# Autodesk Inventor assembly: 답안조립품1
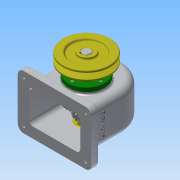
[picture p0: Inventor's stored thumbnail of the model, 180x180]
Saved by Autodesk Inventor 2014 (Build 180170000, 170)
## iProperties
Created: 2016-10
Part Number: 답안조립품1
Document SubType Name: Assembly
Designer: net
Author: net
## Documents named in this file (15)
- C:\Users\net\Desktop\461007V1012\답안조립품1.iam
- C:\Users\net\Desktop\461007V1012\본체.ipt
- C:\Users\net\Desktop\461007V1012\V-벨트풀리.ipt
- C:\Users\net\Desktop\461007V1012\뒤커버.ipt
- C:\Users\net\Desktop\461007V1012\멈춤나사 - M4x10.ipt
- C:\Users\net\Desktop\461007V1012\베어링 6203.ipt
- C:\Users\net\Desktop\461007V1012\볼트 M3 x 8.ipt
- C:\Users\net\Desktop\461007V1012\볼트 M3 x 10.ipt
- C:\Users\net\Desktop\461007V1012\부시.ipt
- C:\Users\net\Desktop\461007V1012\스퍼기어.ipt
- C:\Users\net\Desktop\461007V1012\앞커버.ipt
- C:\Users\net\Desktop\461007V1012\오일씰 28 40 8.ipt
- C:\Users\net\Desktop\461007V1012\축.ipt
- C:\Users\net\Desktop\461007V1012\키 - 5 x 5 x 18.ipt
- C:\Users\net\Desktop\461007V1012\키 - 6 x 6 x 22.ipt
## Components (9 placed, 3 different names)
1. V-벨트풀리:1
2. ISO 4762 M3 x 10:1
3. ISO 4762 M3 x 10:2
4. ISO 4762 M3 x 10:3
5. ISO 4762 M3 x 10:4
6. ISO 4762 M3 x 8:1
7. ISO 4762 M3 x 8:2
8. ISO 4762 M3 x 8:3
9. ISO 4762 M3 x 8:4
